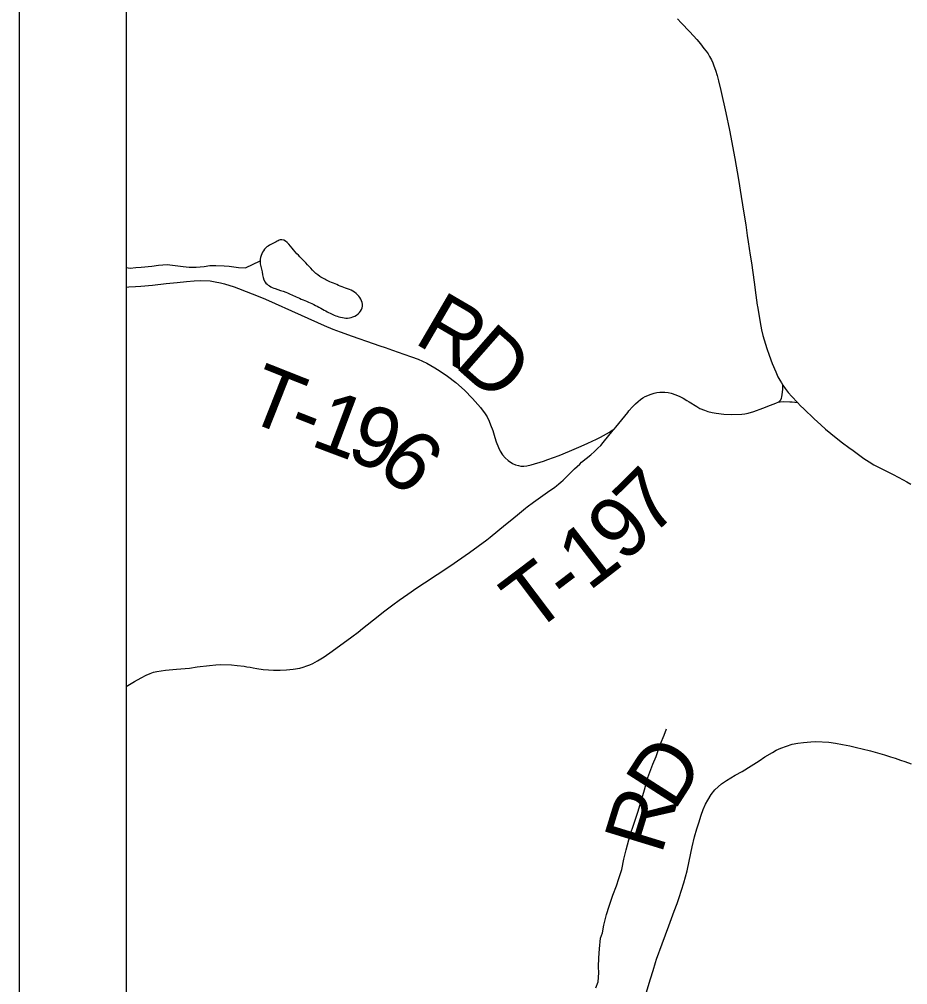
# Model space of a CAD drawing. Extents: x -7.1 to 34, y 0 to 22.
# Drawn here: x 2 to 2.831, y 16.743 to 17.646 of the extents above; entities that cross this region are included whole.
import ezdxf

# ---------------------------------------------------------------- set-up
doc = ezdxf.new("R2010")
doc.units = 0
for name, color, linetype in [('GM_X_County_Road', 7, 'Continuous'), ('GM_X_Minor_River', 7, 'Continuous'), ('GM_X_Township_Road', 7, 'Continuous'), ('GM_X_Township_Road_Text', 7, 'Continuous'), ('SH_Cut_Line', 7, 'Continuous'), ('SH_Data', 7, 'Continuous')]:
    doc.layers.add(name, color=color, linetype=linetype)

msp = doc.modelspace()

# ---------------------------------------------------------------- linework, layer by layer
at = {"layer": 'GM_X_County_Road'}
msp.add_lwpolyline([(2.61543, 17.64611), (2.61879, 17.64255), (2.62678, 17.63404), (2.63329, 17.62687), (2.63692, 17.62267), (2.64011, 17.61857), (2.64215, 17.61596), (2.64386, 17.61334), (2.64525, 17.61095), (2.64704, 17.60777), (2.64834, 17.60499), (2.64943, 17.60231), (2.65085, 17.59805), (2.65235, 17.5933), (2.65374, 17.58812), (2.65583, 17.57919), (2.66042, 17.55837), (2.66387, 17.54194), (2.66889, 17.51564), (2.67228, 17.49589), (2.67494, 17.48014), (2.67729, 17.46451), (2.67911, 17.45349), (2.68047, 17.44359), (2.68144, 17.43752), (2.6834, 17.42527), (2.68445, 17.41801), (2.68575, 17.40915), (2.68698, 17.40007), (2.68866, 17.38766), (2.68985, 17.37831), (2.68999, 17.37731), (2.69316, 17.35896), (2.69379, 17.35553), (2.69518, 17.35012), (2.69887, 17.33792), (2.701, 17.33178), (2.704, 17.32389), (2.70713, 17.31627), (2.70928, 17.31155), (2.7109, 17.30846), (2.71254, 17.3057), (2.7139, 17.30359), (2.71605, 17.30045), (2.7189, 17.29693), (2.72219, 17.29306), (2.72752, 17.28751), (2.73047, 17.28444), (2.73339, 17.28152), (2.74301, 17.27219), (2.74921, 17.26655), (2.75376, 17.2626), (2.76378, 17.2544), (2.76961, 17.24989), (2.77558, 17.24544), (2.77959, 17.24252), (2.78581, 17.23795), (2.78969, 17.23508), (2.79456, 17.23195), (2.79893, 17.22933), (2.80255, 17.22746), (2.80639, 17.22542), (2.81712, 17.22005), (2.82179, 17.21757), (2.82622, 17.21518), (2.82975, 17.21325), (2.83339, 17.21109)], dxfattribs=at)
at = {"layer": 'GM_X_Minor_River'}
for points in [[(2.1, 17.41353), (2.1036, 17.41314), (2.10889, 17.4136), (2.11381, 17.41405), (2.12401, 17.41497), (2.13006, 17.41583), (2.13838, 17.41633), (2.15317, 17.41466), (2.15886, 17.41398), (2.1653, 17.41408), (2.17286, 17.41458), (2.17815, 17.41542), (2.18383, 17.41551), (2.19141, 17.41524), (2.19633, 17.41494), (2.20506, 17.41355), (2.2115, 17.41327), (2.22517, 17.41978)], [(2.59225, 16.9492), (2.59555, 16.95649), (2.59954, 16.96835), (2.60283, 16.9764), (2.60502, 16.98252)], [(2.53885, 16.74012), (2.54104, 16.74587), (2.54167, 16.75425), (2.54159, 16.75996), (2.54185, 16.76834), (2.54248, 16.77673), (2.54348, 16.78664), (2.5453, 16.79162), (2.54633, 16.79887), (2.54884, 16.80881), (2.55138, 16.81646), (2.55501, 16.82679), (2.55829, 16.8356), (2.56046, 16.84249), (2.56337, 16.85091), (2.56513, 16.86045), (2.56727, 16.86924), (2.57123, 16.88339), (2.5745, 16.89334), (2.57812, 16.90444), (2.58029, 16.9117), (2.58464, 16.92548), (2.5875, 16.93694), (2.59225, 16.9492)]]:
    msp.add_lwpolyline(points, dxfattribs=at)
for points in [[(2.24028, 17.43752), (2.2305, 17.43194), (2.22517, 17.41978), (2.22709, 17.40952)], [(2.22709, 17.40952), (2.22976, 17.40002), (2.2393, 17.39394), (2.24921, 17.39052), (2.26027, 17.38558), (2.27362, 17.37988), (2.28659, 17.37305), (2.29727, 17.36811), (2.31023, 17.36697), (2.32051, 17.37609), (2.31631, 17.38825), (2.30335, 17.39509), (2.29038, 17.40041), (2.28084, 17.40535), (2.26787, 17.41789), (2.25643, 17.43004), (2.24384, 17.43954), (2.24028, 17.43752)]]:
    msp.add_spline(points, degree=3, dxfattribs=at)
at = {"layer": 'GM_X_Township_Road'}
for points in [[(2.1, 17.72526), (2.1, 14.1), (6.63303, 14.1), (6.65646, 15.13575), (6.65863, 15.23721), (6.67477, 15.99934), (6.68219, 16.3488), (6.7058, 17.2839), (6.71183, 17.74858)], [(2.1, 17.39542), (2.10248, 17.39545), (2.10878, 17.39576), (2.11356, 17.39611), (2.12467, 17.39725), (2.1372, 17.39861), (2.14767, 17.39972), (2.1564, 17.40064), (2.16337, 17.40118), (2.16936, 17.40145), (2.17838, 17.40107), (2.1831, 17.40038), (2.18806, 17.39933), (2.19191, 17.39831), (2.20081, 17.39547), (2.205, 17.39397), (2.22476, 17.3863), (2.23005, 17.3841), (2.26366, 17.36907), (2.28511, 17.3595), (2.29301, 17.35614), (2.30006, 17.35341), (2.31129, 17.34938), (2.31752, 17.34721), (2.32471, 17.34475), (2.33082, 17.34267), (2.33704, 17.34056), (2.34214, 17.33882), (2.34898, 17.33646), (2.35424, 17.33463), (2.3596, 17.33274), (2.36659, 17.33021), (2.37285, 17.32783), (2.37703, 17.32609), (2.38099, 17.32423), (2.38476, 17.32214), (2.38834, 17.31984), (2.39332, 17.31684), (2.40017, 17.31206), (2.40806, 17.30624), (2.41607, 17.299), (2.42357, 17.29111), (2.4312, 17.28271), (2.43547, 17.27702), (2.43728, 17.27392), (2.43922, 17.26991), (2.44064, 17.26655), (2.44271, 17.26138), (2.44468, 17.25488), (2.44591, 17.25057), (2.44788, 17.24535), (2.44943, 17.24211), (2.45163, 17.23862), (2.45408, 17.23578), (2.45706, 17.23319), (2.4612, 17.23048), (2.46378, 17.22931), (2.46662, 17.22841), (2.46895, 17.22802), (2.47154, 17.22789), (2.47464, 17.22828), (2.47839, 17.22918), (2.49007, 17.23276), (2.49403, 17.23407), (2.50458, 17.23801), (2.51442, 17.24197), (2.52542, 17.24659), (2.53167, 17.24931), (2.53954, 17.2531), (2.54342, 17.25517), (2.55169, 17.25977), (2.55434, 17.26156), (2.55649, 17.26299), (2.55716, 17.26373), (2.55768, 17.26436), (2.56881, 17.27824), (2.56997, 17.27966), (2.57321, 17.28331), (2.57623, 17.28636), (2.57855, 17.28851), (2.58086, 17.29038), (2.58305, 17.29185), (2.58511, 17.29299), (2.5906, 17.29531), (2.59344, 17.29621), (2.59604, 17.29682), (2.59875, 17.29717), (2.60125, 17.29725), (2.60337, 17.29717), (2.60671, 17.29673), (2.60934, 17.29611), (2.61363, 17.29468), (2.61745, 17.29304), (2.6206, 17.29143), (2.62405, 17.28943), (2.6261, 17.28813), (2.63337, 17.28357), (2.63635, 17.28198), (2.64051, 17.2802), (2.64374, 17.27915), (2.64774, 17.27818), (2.65151, 17.27753), (2.65876, 17.27671), (2.66566, 17.27629), (2.67555, 17.27652), (2.67833, 17.27692), (2.68131, 17.27758), (2.68658, 17.27918), (2.69501, 17.28216), (2.70237, 17.28487), (2.70731, 17.28676), (2.70993, 17.28803), (2.71067, 17.28857), (2.71194, 17.28989), (2.71262, 17.29141), (2.71304, 17.29272), (2.71331, 17.29487), (2.71372, 17.29958), (2.7139, 17.30359)], [(2.70993, 17.28803), (2.71141, 17.28817), (2.71439, 17.28838), (2.72043, 17.28823), (2.72264, 17.28808), (2.72514, 17.28778), (2.72752, 17.28751)], [(2.23774, 17.03722), (2.24386, 17.03713), (2.2498, 17.0374), (2.256, 17.03812), (2.26212, 17.0392), (2.26536, 17.04001), (2.26885, 17.04112), (2.27157, 17.04217), (2.27448, 17.04348), (2.27892, 17.046), (2.28487, 17.04982), (2.29246, 17.05496), (2.3108, 17.06835), (2.31682, 17.07276), (2.32096, 17.07618), (2.33545, 17.08778), (2.3405, 17.09169), (2.34534, 17.09544), (2.34912, 17.0984), (2.35515, 17.10272), (2.36333, 17.10834), (2.37163, 17.11404), (2.37872, 17.11891), (2.40264, 17.13446), (2.42101, 17.14725), (2.43703, 17.15894), (2.44023, 17.16142), (2.45465, 17.17325), (2.46057, 17.17821), (2.4676, 17.18412), (2.4732, 17.18881), (2.47472, 17.19005), (2.48065, 17.19439), (2.48731, 17.19898), (2.4939, 17.20359), (2.50063, 17.20834), (2.50207, 17.20949), (2.50441, 17.21131), (2.50637, 17.21313), (2.50837, 17.21491), (2.51398, 17.22036), (2.51909, 17.22532), (2.52388, 17.22985), (2.52573, 17.23153), (2.53419, 17.23839), (2.53769, 17.24154), (2.54093, 17.24469), (2.54354, 17.2473), (2.54592, 17.25003), (2.55534, 17.26158), (2.55649, 17.26299)], [(2.1, 17.02184), (2.10771, 17.02655), (2.11377, 17.03003), (2.11874, 17.03259), (2.12225, 17.03414), (2.12542, 17.03519), (2.12863, 17.03592), (2.13267, 17.0366), (2.13663, 17.03708), (2.14705, 17.03803), (2.15904, 17.03923), (2.1663, 17.04019), (2.17766, 17.04162), (2.18377, 17.04226), (2.18853, 17.04253), (2.19825, 17.04226), (2.20355, 17.04172), (2.21019, 17.04083), (2.21279, 17.04043), (2.21587, 17.03992), (2.21876, 17.03939), (2.222, 17.03875), (2.22802, 17.03794), (2.23297, 17.03749), (2.23774, 17.03722)], [(2.58612, 16.73531), (2.59012, 16.74853), (2.59247, 16.7563), (2.59475, 16.76382), (2.59576, 16.76698), (2.60112, 16.78144), (2.6073, 16.79809), (2.61237, 16.81175), (2.61491, 16.81897), (2.61686, 16.82481), (2.61903, 16.83147), (2.62117, 16.83838), (2.62277, 16.8439), (2.62423, 16.84948), (2.62626, 16.85849), (2.62914, 16.87201), (2.63138, 16.88151), (2.63348, 16.8888), (2.63516, 16.89451), (2.6376, 16.90179), (2.63948, 16.90692), (2.6416, 16.91191), (2.6436, 16.91567), (2.64684, 16.92091), (2.65035, 16.92541), (2.65322, 16.92829), (2.65647, 16.93103), (2.66122, 16.93391), (2.66941, 16.93902), (2.67573, 16.94262), (2.68434, 16.94765), (2.69168, 16.95244), (2.69711, 16.95608), (2.70428, 16.96031), (2.70771, 16.96227), (2.71196, 16.96427), (2.7172, 16.96628), (2.7227, 16.9679), (2.72783, 16.9689), (2.73307, 16.96965), (2.73995, 16.97027), (2.74482, 16.9704), (2.75669, 16.9699), (2.76307, 16.96902), (2.76969, 16.96779), (2.77649, 16.96649), (2.78278, 16.96505), (2.78813, 16.96368), (2.79575, 16.96165), (2.80233, 16.95981), (2.80874, 16.95795), (2.81435, 16.95626), (2.81888, 16.95484), (2.82394, 16.95318), (2.82773, 16.9519), (2.83392, 16.94978)]]:
    msp.add_lwpolyline(points, dxfattribs=at)
at = {"layer": 'SH_Cut_Line'}
msp.add_lwpolyline([(2.1, 17.72526), (2.1, 14.1), (8.9, 14.1), (8.9, 17.7079), (8.66678, 17.71356), (8.44721, 17.71888), (7.7202, 17.72853), (6.71183, 17.74858), (6.3575, 17.75566), (6.1904, 17.7592), (5.75143, 17.76848), (5.50466, 17.77369), (5.11149, 17.78191), (5.05435, 17.78311), (5.04428, 17.78316), (4.70941, 17.78483), (4.56567, 17.78571), (4.30003, 17.78734), (3.83037, 17.79518), (3.82383, 17.67174), (3.72149, 17.67065), (3.06595, 17.69863), (2.7886, 17.71047), (2.55513, 17.71548)], close=True, dxfattribs=at)
at = {"layer": 'SH_Data'}
for p, q in [((2, 21), (2, 14)), ((2.1, 20.9), (2.1, 14.1))]:
    msp.add_line(p, q, dxfattribs=at)

# ---------------------------------------------------------------- texts
at = {"layer": 'GM_X_Township_Road_Text'}
for s, rotation, p in [('R', 329.72067, (2.3677, 17.34379)), ('D', 318.67564, (2.40565, 17.32195)), ('T', 338.4071, (2.20863, 17.27231)), ('1', 339.38236, (2.27085, 17.24776)), ('9', 339.70779, (2.30394, 17.23532)), ('-', 338.57046, (2.24831, 17.2566)), ('6', 318.36517, (2.332, 17.22604)), ('7', 44.65865, (2.591, 17.16103)), ('9', 43.89628, (2.56518, 17.13619)), ('1', 37.67597, (2.53239, 17.11041)), ('T', 37.05931, (2.47936, 17.07029)), ('-', 37.17303, (2.51337, 17.09598)), ('D', 57.40419, (2.61219, 16.90457)), ('R', 72.89999, (2.60017, 16.86365))]:
    msp.add_text(s, height=0.05682, rotation=rotation, dxfattribs=at).set_placement(p)

doc.saveas('drawing.dxf')
